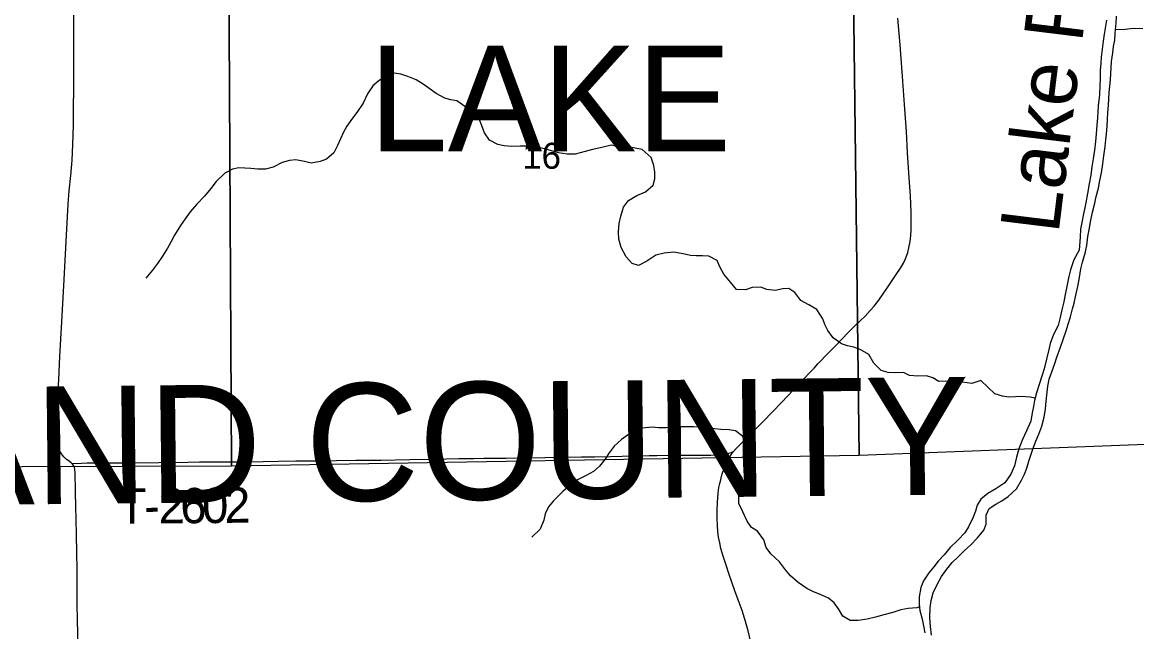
# Model space of a CAD drawing. Extents: x 0 to 34, y 0 to 22.
# Drawn here: x 5.733 to 7.526, y 19.466 to 20.447 of the extents above; entities that cross this region are included whole.
import ezdxf

# ---------------------------------------------------------------- set-up
doc = ezdxf.new("R2010")
doc.units = 0
for name, color, linetype in [('GM_X_County_Road_Text', 7, 'Continuous'), ('GM_X_Interchange_Ramps', 7, 'Continuous'), ('GM_X_Major_River', 7, 'Continuous'), ('GM_X_Rail_Line', 7, 'Continuous'), ('GM_X_State_Location', 7, 'Continuous'), ('GM_X_State_Route', 7, 'Continuous'), ('GM_X_State_Shield', 7, 'Continuous'), ('GM_X_Township_Road', 7, 'Continuous'), ('GM_X_Township_Text', 7, 'Continuous'), ('GM_X_Unincorporated_Location', 7, 'Continuous')]:
    doc.layers.add(name, color=color, linetype=linetype)

msp = doc.modelspace()

# ---------------------------------------------------------------- linework, layer by layer
at = {"layer": 'GM_X_County_Road_Text'}
for points in [[(7.4924, 20.4356), (7.5077, 20.4359), (7.5213, 20.4375), (7.5361, 20.4371)], [(6.4129, 20.3247), (6.3988, 20.3323), (6.3893, 20.3395), (6.3783, 20.3474), (6.3669, 20.3542), (6.3536, 20.3598), (6.3422, 20.3636), (6.3316, 20.365), (6.3195, 20.3612), (6.3074, 20.3532), (6.2972, 20.3448), (6.2886, 20.3319), (6.2814, 20.3167), (6.2716, 20.3018), (6.2626, 20.2904), (6.255, 20.2797), (6.2498, 20.2699), (6.2449, 20.2592), (6.2404, 20.2486), (6.2344, 20.2368), (6.2227, 20.2269), (6.2125, 20.223), (6.1977, 20.2203), (6.1871, 20.2229), (6.1734, 20.2255), (6.1628, 20.2247), (6.1511, 20.2213), (6.1367, 20.214), (6.1242, 20.2106), (6.1117, 20.2105), (6.1007, 20.2116), (6.0912, 20.2123), (6.0817, 20.2127), (6.0715, 20.2104), (6.0587, 20.2042), (6.0451, 20.1905), (6.0364, 20.1795), (6.0262, 20.1669), (6.0138, 20.154), (6.0032, 20.1418), (5.9953, 20.1304), (5.9874, 20.1197), (5.978, 20.1045), (5.972, 20.0931), (5.9667, 20.0832), (5.9588, 20.0703), (5.9505, 20.0589), (5.9426, 20.0482), (5.932, 20.0353)], [(7.3631, 19.8421), (7.3548, 19.8437), (7.3415, 19.8448), (7.3316, 19.8443), (7.3207, 19.8435), (7.3104, 19.8454), (7.2979, 19.8491), (7.2758, 19.8703), (7.2611, 19.8657), (7.2459, 19.8675), (7.2341, 19.8728), (7.2235, 19.8694), (7.208, 19.8685), (7.1981, 19.8746), (7.1883, 19.878), (7.1742, 19.8775), (7.1606, 19.8782), (7.1511, 19.8831), (7.1374, 19.8827), (7.1265, 19.883), (7.1151, 19.8864), (7.1033, 19.8981), (7.0956, 19.9121), (7.0812, 19.9201), (7.0713, 19.9238), (7.0611, 19.9261), (7.0512, 19.9294), (7.0379, 19.9389), (7.0292, 19.9506), (7.0246, 19.9605), (7.0211, 19.9699), (7.0116, 19.9847), (6.9987, 19.9922), (6.9858, 19.9994), (6.9762, 20.0119), (6.9667, 20.0183), (6.9569, 20.0179), (6.9444, 20.0152), (6.9311, 20.0166), (6.9216, 20.0208), (6.9076, 20.0203), (6.897, 20.0161), (6.8826, 20.0168), (6.8727, 20.0286), (6.862, 20.0418), (6.8555, 20.0532), (6.8513, 20.0638), (6.8377, 20.0706), (6.8278, 20.0709), (6.8176, 20.0709), (6.8081, 20.0716), (6.7967, 20.0742), (6.7808, 20.0768), (6.766, 20.0752), (6.7528, 20.0721), (6.738, 20.0622), (6.7248, 20.0557), (6.7145, 20.0587), (6.705, 20.0693), (6.697, 20.0844), (6.6931, 20.0977), (6.6923, 20.1095), (6.6934, 20.1231), (6.696, 20.1349), (6.7005, 20.1494), (6.7088, 20.16), (6.7217, 20.168), (6.736, 20.1738), (6.7481, 20.1848), (6.7507, 20.1951), (6.7507, 20.2057), (6.7491, 20.2163), (6.7453, 20.2292), (6.7308, 20.2424), (6.7168, 20.2451), (6.7073, 20.2454), (6.6929, 20.2465), (6.6808, 20.2491), (6.6637, 20.2449), (6.6505, 20.2421), (6.6387, 20.2391), (6.6228, 20.2345), (6.61, 20.2348), (6.5959, 20.237), (6.583, 20.2408), (6.5713, 20.2437), (6.5569, 20.2463), (6.5451, 20.2478), (6.5341, 20.2474), (6.5205, 20.2473), (6.5087, 20.2481), (6.4981, 20.2503), (6.4848, 20.2571), (6.4768, 20.2692), (6.471, 20.2847), (6.4668, 20.2957), (6.4566, 20.3071), (6.4467, 20.3104), (6.4322, 20.3206), (6.4224, 20.3221), (6.4129, 20.3247)], [(7.1767, 19.506), (7.1724, 19.5045), (7.1584, 19.5033), (7.147, 19.501), (7.1337, 19.4971), (7.1197, 19.4933), (7.1061, 19.4894), (7.0929, 19.4863), (7.0781, 19.484), (7.0652, 19.4843), (7.0534, 19.4911), (7.0466, 19.5029), (7.0397, 19.5127), (7.0302, 19.5199), (7.0161, 19.5263), (7.0063, 19.5304), (6.9956, 19.5353), (6.9816, 19.5451), (6.9694, 19.5557), (6.9614, 19.5655), (6.9515, 19.5784), (6.9374, 19.5913), (6.9302, 19.6015), (6.9263, 19.614), (6.9164, 19.628), (6.9065, 19.634), (6.8997, 19.6442), (6.8924, 19.659), (6.8859, 19.6726), (6.8859, 19.6863), (6.8915, 19.6992), (6.8971, 19.7106), (6.9012, 19.7236), (6.9039, 19.735), (6.9061, 19.7444), (6.9041, 19.7592), (6.8992, 19.771), (6.8919, 19.7808), (6.8809, 19.7895), (6.8703, 19.791), (6.857, 19.7917), (6.8468, 19.7928), (6.8362, 19.7939), (6.8233, 19.795), (6.813, 19.7957), (6.8035, 19.7957), (6.7929, 19.796), (6.7816, 19.7952), (6.7694, 19.7944), (6.7569, 19.7944), (6.7471, 19.7951), (6.7308, 19.7935), (6.7206, 19.7904), (6.7085, 19.7836), (6.6971, 19.7755), (6.6854, 19.7649), (6.6775, 19.7538), (6.6707, 19.7432), (6.6621, 19.7325), (6.6523, 19.7238), (6.6402, 19.7173), (6.6277, 19.7111), (6.6152, 19.7024), (6.6027, 19.6917), (6.5876, 19.6768), (6.5797, 19.6669), (6.5745, 19.6559), (6.5722, 19.6453), (6.5662, 19.6308), (6.553, 19.6183)]]:
    msp.add_lwpolyline(points, dxfattribs=at)
at = {"layer": 'GM_X_Interchange_Ramps'}
for points in [[(5.8129, 19.7369), (5.8118, 19.7379), (5.8067, 19.7414), (5.8042, 19.7433), (5.8019, 19.7454), (5.7997, 19.7476), (5.7977, 19.75), (5.7959, 19.7525), (5.7942, 19.7551), (5.7927, 19.7578), (5.7914, 19.7607), (5.7902, 19.7635), (5.7885, 19.7695), (5.7874, 19.7756), (5.787, 19.7818), (5.7871, 19.788), (5.7877, 19.8004), (5.7898, 19.8345), (5.7916, 19.8718), (5.7935, 19.909), (5.7946, 19.9276), (5.797, 19.9742), (5.8004, 20.0331), (5.8025, 20.0735), (5.8042, 20.1045), (5.807, 20.1541), (5.8085, 20.1758), (5.8108, 20.2006), (5.8131, 20.2253), (5.8144, 20.2501), (5.8154, 20.2812), (5.8156, 20.306), (5.8157, 20.3433), (5.8159, 20.3712), (5.8161, 20.4114), (5.8161, 20.4609)], [(5.8129, 19.7369), (5.8282, 19.7375), (5.8375, 19.7379), (5.8624, 19.7379), (5.9059, 19.738), (5.9526, 19.7385), (5.9992, 19.7388), (6.0179, 19.7392), (6.0458, 19.7396), (6.0769, 19.7397), (6.1204, 19.7402), (6.1453, 19.7406), (6.1733, 19.7409), (6.2074, 19.7413), (6.2696, 19.7419), (6.31, 19.7424), (6.3567, 19.7431), (6.3909, 19.7437), (6.4157, 19.7444), (6.4353, 19.7447), (6.4597, 19.7449), (6.4757, 19.7451), (6.4932, 19.7452), (6.5119, 19.7453), (6.5429, 19.746), (6.574, 19.7464), (6.6329, 19.7473), (6.6546, 19.7475), (6.6795, 19.7479), (6.6981, 19.7484), (6.7292, 19.7492), (6.7416, 19.7496), (6.754, 19.7498), (6.7911, 19.7502), (6.8315, 19.7503), (6.8408, 19.7501), (6.8569, 19.7507)], [(6.8569, 19.7507), (6.8624, 19.7513), (6.8658, 19.7521), (6.8698, 19.7533), (6.8738, 19.7546), (6.8778, 19.7562)], [(6.8569, 19.7507), (6.8595, 19.7493), (6.8617, 19.7476), (6.8633, 19.7456), (6.8652, 19.7425), (6.8666, 19.7384)], [(5.8227, 19.4354), (5.8221, 19.4665), (5.8218, 19.482), (5.8215, 19.513), (5.8215, 19.5286), (5.8211, 19.5628), (5.8207, 19.5969), (5.8204, 19.6187), (5.8196, 19.6496), (5.8191, 19.6651), (5.8184, 19.6931), (5.8178, 19.7211), (5.8174, 19.7273), (5.8168, 19.7304), (5.8157, 19.7332), (5.814, 19.7358), (5.8129, 19.7369)]]:
    msp.add_lwpolyline(points, dxfattribs=at)
at = {"layer": 'GM_X_State_Route'}
for points in [[(7.0675, 20.7541), (8.0394, 20.7862), (8.0588, 19.7873), (7.0797, 19.7498)], [(6.064, 20.7377), (7.0675, 20.7541), (7.0797, 19.7498), (6.0697, 19.7327)], [(5.0487, 20.73), (6.064, 20.7377), (6.0697, 19.7327), (5.0579, 19.7292)]]:
    msp.add_lwpolyline(points, close=True, dxfattribs=at)
at = {"layer": 'GM_X_State_Shield'}
for points in [[(7.2391, 19.5867), (7.2493, 19.5966), (7.2591, 19.6054), (7.2704, 19.6172), (7.2802, 19.6297), (7.284, 19.6392), (7.2843, 19.6537), (7.2888, 19.6643), (7.2998, 19.6712), (7.3096, 19.6769), (7.3198, 19.6834), (7.333, 19.696), (7.3409, 19.7097), (7.3458, 19.7195), (7.3496, 19.7294), (7.3529, 19.7404), (7.3559, 19.7503), (7.3597, 19.7617), (7.3642, 19.7727), (7.369, 19.7838), (7.3735, 19.7967), (7.3776, 19.8115), (7.3795, 19.8248), (7.3809, 19.8369), (7.3824, 19.8514), (7.3835, 19.8612), (7.3857, 19.8726), (7.3898, 19.8844), (7.3947, 19.8977), (7.3981, 19.908), (7.4037, 19.9239), (7.4086, 19.938), (7.4131, 19.9505), (7.4164, 19.9612), (7.4198, 19.9726), (7.4232, 19.9855), (7.4258, 19.995), (7.4287, 20.0079), (7.4317, 20.0216), (7.4343, 20.036), (7.4365, 20.05), (7.4391, 20.0607), (7.4436, 20.0755), (7.4462, 20.0877), (7.4477, 20.1021), (7.4503, 20.1158), (7.4521, 20.1256), (7.4555, 20.1416), (7.4588, 20.156), (7.4614, 20.1666), (7.4648, 20.1799), (7.467, 20.1921), (7.4696, 20.2046), (7.4722, 20.2194), (7.4737, 20.232), (7.4755, 20.2468), (7.477, 20.2578), (7.4781, 20.2673), (7.4788, 20.2798), (7.4795, 20.2912), (7.4802, 20.3018), (7.4809, 20.3136), (7.4816, 20.3238), (7.482, 20.3341), (7.4831, 20.344), (7.4842, 20.3542), (7.4849, 20.3645), (7.4856, 20.3739), (7.4859, 20.3838), (7.4878, 20.3979), (7.4892, 20.4081), (7.4911, 20.4184), (7.4918, 20.4294), (7.4933, 20.4457), (7.494, 20.4567)], [(7.4777, 20.4506), (7.4762, 20.4407), (7.474, 20.4278), (7.4725, 20.4164), (7.4707, 20.4035), (7.4692, 20.3906), (7.4685, 20.3811), (7.4678, 20.3697), (7.4675, 20.356), (7.4671, 20.345), (7.4665, 20.3302), (7.4646, 20.3124), (7.4632, 20.2934), (7.4625, 20.2816), (7.461, 20.2672), (7.4603, 20.2551), (7.4585, 20.2414), (7.4566, 20.2273), (7.4544, 20.2144), (7.4526, 20.2008), (7.45, 20.1867), (7.4474, 20.1715), (7.4444, 20.1563), (7.4407, 20.1385), (7.4381, 20.1248), (7.4359, 20.1138), (7.4352, 20.1009), (7.4338, 20.08), (7.4255, 20.0648), (7.4199, 20.0485), (7.4173, 20.0378), (7.4143, 20.0242), (7.4113, 20.009), (7.4091, 19.9972), (7.4057, 19.9843), (7.4028, 19.9698), (7.3998, 19.9588), (7.3926, 19.9444), (7.3874, 19.9299), (7.3848, 19.9204), (7.3814, 19.9045), (7.3773, 19.8893), (7.374, 19.8775), (7.3695, 19.8638), (7.3653, 19.8505), (7.362, 19.838), (7.3601, 19.8285), (7.3583, 19.8183), (7.3561, 19.805), (7.3489, 19.7894), (7.3429, 19.7753), (7.3365, 19.7605), (7.3332, 19.7472), (7.3298, 19.7331), (7.3238, 19.7195), (7.314, 19.7058), (7.2997, 19.6962), (7.2868, 19.6886), (7.2755, 19.6791), (7.2698, 19.6695)], [(7.2698, 19.6695), (7.2668, 19.66), (7.2635, 19.6502), (7.256, 19.635), (7.2499, 19.6254), (7.2386, 19.6136), (7.2262, 19.6018), (7.2167, 19.59), (7.2069, 19.5797), (7.2001, 19.5702), (7.1918, 19.5607), (7.1832, 19.5478), (7.1791, 19.5371), (7.1765, 19.5223), (7.1761, 19.5106), (7.1773, 19.5003), (7.1812, 19.4863), (7.1835, 19.4757), (7.1854, 19.4643)], [(7.196, 19.4602), (7.1945, 19.4746), (7.1933, 19.489), (7.1943, 19.5042), (7.1958, 19.5163), (7.1988, 19.5285), (7.2052, 19.5418), (7.2123, 19.5547), (7.221, 19.5669), (7.2293, 19.5772), (7.2391, 19.5867)]]:
    msp.add_lwpolyline(points, dxfattribs=at)
at = {"layer": 'GM_X_Township_Road'}
for points in [[(6.8778, 19.7562), (6.8819, 19.7611), (6.8859, 19.7652), (6.8957, 19.775), (6.913, 19.7923), (6.9241, 19.8032), (6.9413, 19.821), (6.9543, 19.8344), (6.9649, 19.8457), (6.9797, 19.8614), (7.0011, 19.8836), (7.0073, 19.8903), (7.0135, 19.897), (7.0305, 19.9148), (7.0412, 19.9259), (7.0519, 19.9371), (7.0627, 19.9482), (7.0736, 19.9591), (7.0892, 19.9741), (7.0977, 19.9831), (7.1038, 19.9901), (7.1113, 19.9999), (7.1255, 20.0203), (7.1394, 20.0409), (7.1463, 20.0512), (7.1511, 20.0595), (7.1537, 20.0649), (7.1559, 20.0707), (7.1579, 20.0765), (7.1599, 20.084), (7.1616, 20.0939), (7.1628, 20.1037), (7.1635, 20.1129), (7.1637, 20.1253), (7.1634, 20.1408), (7.1624, 20.1676), (7.1603, 20.1966), (7.1577, 20.2369), (7.1557, 20.271), (7.153, 20.3144), (7.1492, 20.3671), (7.1473, 20.3888), (7.1456, 20.4105), (7.1442, 20.429), (7.1421, 20.4538)], [(6.8666, 19.7384), (6.8715, 19.7475), (6.8743, 19.7517), (6.8778, 19.7562)], [(6.9052, 19.4492), (6.9009, 19.4673), (6.8969, 19.4822), (6.8913, 19.4999), (6.8852, 19.5174), (6.8799, 19.532), (6.8706, 19.5583), (6.8655, 19.573), (6.8608, 19.5878), (6.8574, 19.5998), (6.8553, 19.6089), (6.8536, 19.6181), (6.8524, 19.6273), (6.8516, 19.6367), (6.8512, 19.6491), (6.8513, 19.6616), (6.8517, 19.674), (6.8528, 19.6895), (6.8542, 19.6983), (6.8554, 19.7045), (6.8571, 19.7107), (6.8584, 19.7165), (6.86, 19.7219), (6.8634, 19.7309), (6.8653, 19.7354), (6.8666, 19.7384)]]:
    msp.add_lwpolyline(points, dxfattribs=at)

# ---------------------------------------------------------------- texts
at = {"layer": 'GM_X_Major_River'}
msp.add_text('LAKE', height=0.17045, rotation=0, dxfattribs=at).set_placement((6.291, 20.2391))
at = {"layer": 'GM_X_Rail_Line'}
msp.add_text('ASHLAND COUNTY', height=0.189394, rotation=0.605, dxfattribs=at).set_placement((4.9228, 19.6623))
at = {"layer": 'GM_X_State_Location'}
msp.add_text('16', height=0.04186, rotation=0, dxfattribs=at).set_placement((6.5376, 20.2112))
at = {"layer": 'GM_X_Township_Text'}
for s, rotation, p in [('T', 0.2443, (5.8865, 19.64)), ('2', 0.2592, (5.9524, 19.6403)), ('6', 0.3078, (5.9874, 19.6405)), ('0', 0.4521, (6.0226, 19.6407)), ('2', 1.169, (6.0584, 19.641)), ('-', 0.2557, (5.9291, 19.6402))]:
    msp.add_text(s, height=0.0568, rotation=rotation, dxfattribs=at).set_placement(p)
at = {"layer": 'GM_X_Unincorporated_Location'}
msp.add_text('Lake Fork', height=0.09472, rotation=82.9891, dxfattribs=at).set_placement((7.4005, 20.1051))

doc.saveas('drawing.dxf')
